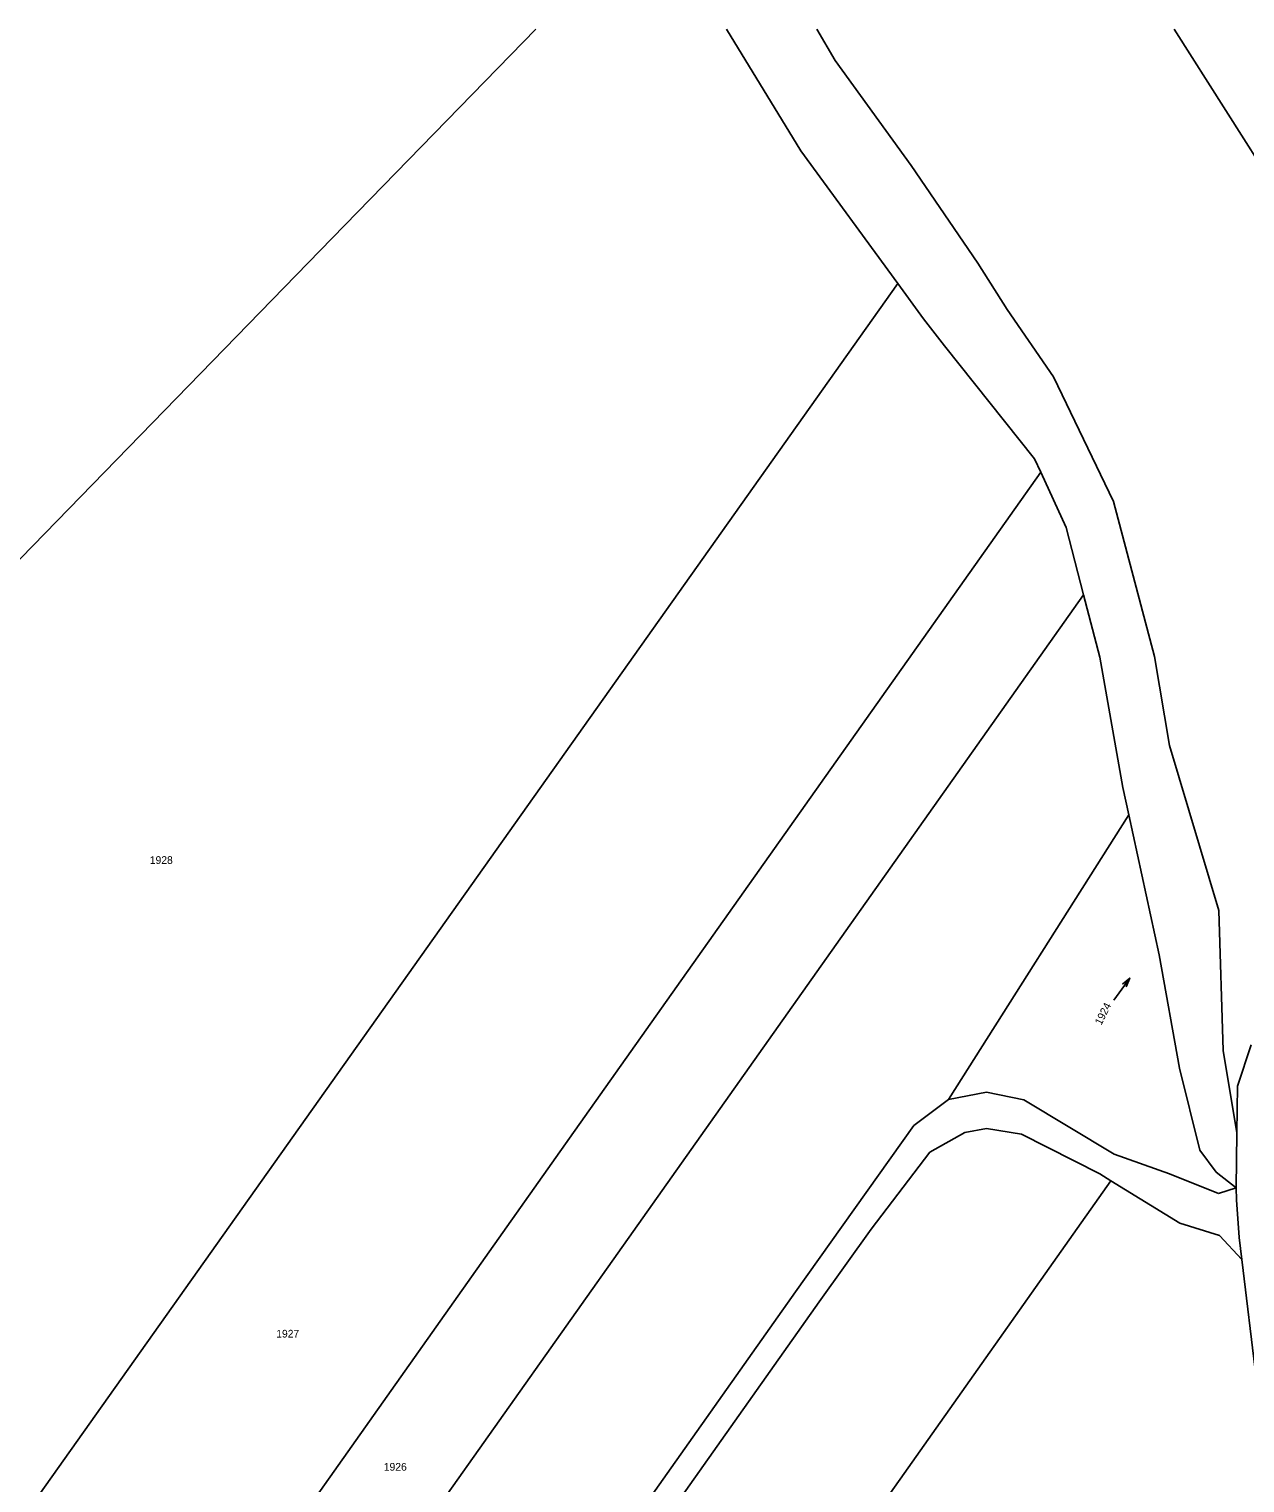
# Model space of a CAD drawing. Extents: x -801853 to -800578, y -1017479 to -1016338.
# Drawn here: x -801685.9 to -801418.1, y -1016658 to -1016337.6 of the extents above; entities that cross this region are included whole.
import ezdxf

# ---------------------------------------------------------------- set-up
doc = ezdxf.new("R2010")
doc.units = 0
for name, color, linetype in [('Default', 7, 'Continuous'), ('KN_HRANICE', 7, 'Continuous'), ('KN_KULTURY', 7, 'Continuous'), ('KN_PARCELY', 7, 'Continuous')]:
    doc.layers.add(name, color=color, linetype=linetype)

# ---------------------------------------------------------------- blocks, each defined once
blk = doc.blocks.new('802')
at = {"layer": 'Default'}
blk.add_line((-3, 0), (3, 0), dxfattribs=at)
blk.add_lwpolyline([(1, 0.5), (3, 0), (1, -0.5)], dxfattribs=at)

msp = doc.modelspace()

# ---------------------------------------------------------------- linework, layer by layer
at = {"layer": 'KN_HRANICE'}
for p, q in [((-801619.17, -1016383.72), (-801574.32, -1016337.63)), ((-801532.29, -1016337.63), (-801515.9, -1016364.45)), ((-801508.36, -1016344.57), (-801512.4, -1016337.63)), ((-801356.93, -1016458.73), (-801433.65, -1016337.63)), ((-801491.62, -1016367.69), (-801508.36, -1016344.57)), ((-801515.9, -1016364.45), (-801494.57, -1016393.69)), ((-801476.92, -1016389.19), (-801491.62, -1016367.69)), ((-801703.82, -1016470.7), (-801619.17, -1016383.72)), ((-801470.45, -1016399.41), (-801476.92, -1016389.19)), ((-801596.87, -1016538.03), (-801494.57, -1016393.69)), ((-801494.57, -1016393.69), (-801488.91, -1016401.46)), ((-801488.91, -1016401.46), (-801484.23, -1016407.41)), ((-801460.25, -1016414.28), (-801470.45, -1016399.41)), ((-801484.23, -1016407.41), (-801464.42, -1016432.32)), ((-801447.02, -1016441.69), (-801460.25, -1016414.28)), ((-801464.42, -1016432.32), (-801463.06, -1016435.28)), ((-801566.87, -1016582.04), (-801463.06, -1016435.28)), ((-801463.06, -1016435.28), (-801457.49, -1016447.46)), ((-801438.03, -1016475.85), (-801447.02, -1016441.69)), ((-801457.49, -1016447.46), (-801453.63, -1016462.27)), ((-801552.88, -1016602.56), (-801453.63, -1016462.27)), ((-801453.63, -1016462.27), (-801450.05, -1016475.99)), ((-801450.05, -1016475.99), (-801444.94, -1016504.77)), ((-801434.7, -1016495.46), (-801438.03, -1016475.85)), ((-801423.81, -1016531.84), (-801434.7, -1016495.46)), ((-801444.94, -1016504.77), (-801443.64, -1016510.78)), ((-801483.41, -1016573.47), (-801443.64, -1016510.78)), ((-801443.64, -1016510.78), (-801436.97, -1016541.64)), ((-801422.85, -1016562.67), (-801423.81, -1016531.84)), ((-801683.77, -1016660.64), (-801596.87, -1016538.03)), ((-801436.97, -1016541.64), (-801432.49, -1016566.57)), ((-801419.68, -1016570.55), (-801416.73, -1016561.43)), ((-801419.84, -1016580.8), (-801422.85, -1016562.67)), ((-801432.49, -1016566.57), (-801428.02, -1016584.68)), ((-801419.84, -1016580.8), (-801419.68, -1016570.55)), ((-801483.41, -1016573.47), (-801491.05, -1016579.18)), ((-801474.98, -1016571.89), (-801483.41, -1016573.47)), ((-801466.77, -1016573.54), (-801474.98, -1016571.89)), ((-801446.85, -1016585.51), (-801466.77, -1016573.54)), ((-801491.05, -1016579.18), (-801517.05, -1016615.83)), ((-801487.47, -1016585.11), (-801479.77, -1016580.74)), ((-801475, -1016579.85), (-801479.77, -1016580.74)), ((-801475, -1016579.85), (-801467.27, -1016581.11)), ((-801467.27, -1016581.11), (-801450.06, -1016589.85)), ((-801420.02, -1016592.97), (-801419.84, -1016580.8)), ((-801653.68, -1016704.77), (-801566.87, -1016582.04)), ((-801500.43, -1016602.03), (-801487.47, -1016585.11)), ((-801434.72, -1016589.88), (-801446.85, -1016585.51)), ((-801428.02, -1016584.68), (-801424.44, -1016589.5)), ((-801450.06, -1016589.85), (-801447.6, -1016591.37)), ((-801423.93, -1016594.19), (-801434.72, -1016589.88)), ((-801424.44, -1016589.5), (-801420.02, -1016592.97)), ((-801447.6, -1016591.37), (-801541.38, -1016724.15)), ((-801447.6, -1016591.37), (-801432.42, -1016600.72)), ((-801420.02, -1016592.97), (-801423.93, -1016594.19)), ((-801419.93, -1016595.58), (-801420.02, -1016592.97)), ((-801419.32, -1016603.92), (-801419.93, -1016595.58)), ((-801639.69, -1016725.29), (-801552.88, -1016602.56)), ((-801511.85, -1016618.06), (-801500.43, -1016602.03)), ((-801432.42, -1016600.72), (-801423.64, -1016603.45)), ((-801423.64, -1016603.45), (-801418.74, -1016608.77)), ((-801418.74, -1016608.77), (-801419.32, -1016603.92)), ((-801415.62, -1016634.88), (-801418.74, -1016608.77)), ((-801575.59, -1016698.58), (-801517.05, -1016615.83)), ((-801571.59, -1016702.44), (-801511.85, -1016618.06))]:
    msp.add_line(p, q, dxfattribs=at)

# ---------------------------------------------------------------- block references
at = {"layer": 'KN_KULTURY', "rotation": 54.43099100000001}
msp.add_blockref('802', (-801445.19, -1016549.17), dxfattribs=at)

# ---------------------------------------------------------------- texts
at = {"layer": 'KN_PARCELY'}
for s, p in [('1928', (-801659.33, -1016521.58)), ('1927', (-801631.48, -1016625.94)), ('1926', (-801607.78, -1016655.27))]:
    msp.add_text(s, height=1.7, dxfattribs=at).set_placement(p)
msp.add_text('1924', height=1.7, rotation=63.484, dxfattribs=at).set_placement((-801449.73, -1016557.23))

doc.saveas('drawing.dxf')
